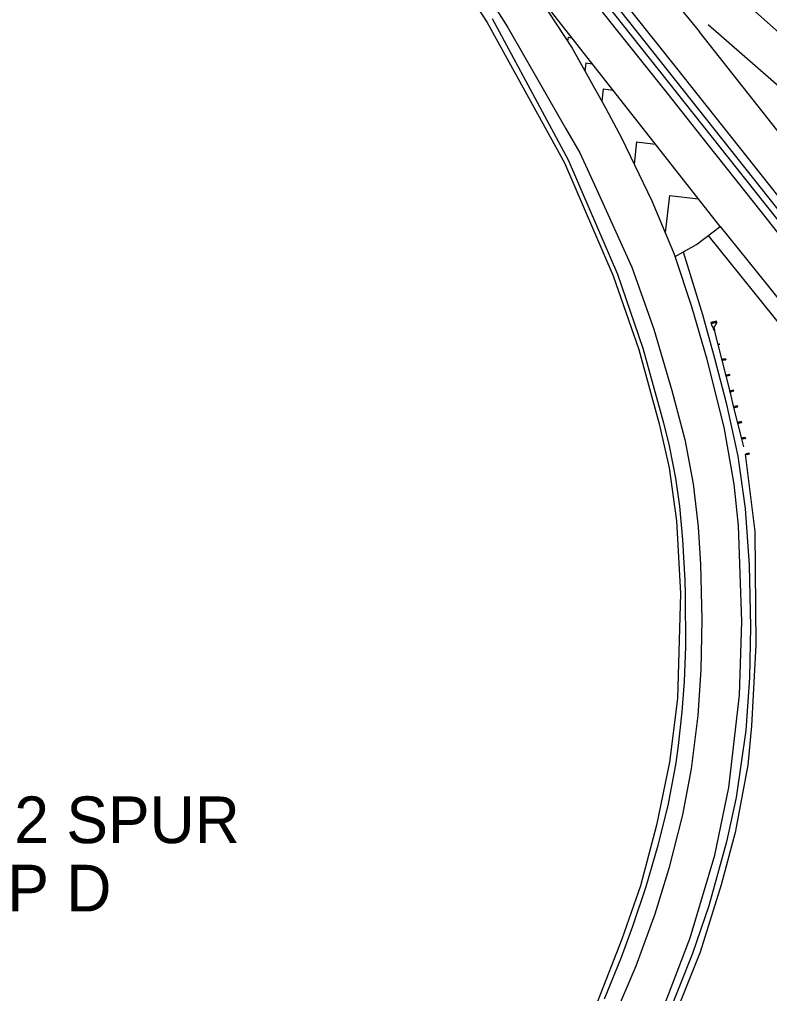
# Model space of a CAD drawing. Extents: x 1855721 to 1876784, y 662259 to 674089.
# Drawn here: x 1856991.1 to 1857280.3, y 672641.1 to 673016.5 of the extents above; entities that cross this region are included whole.
import ezdxf

# ---------------------------------------------------------------- set-up
doc = ezdxf.new("R2010")
doc.units = 0
for name, color, linetype in [('_CIVIL_CONSTRUCTION', 7, 'Continuous'), ('GE_X_Alignment_100_Cardinal_Points', 7, 'Continuous'), ('GE_X_Alignment_100_Curve_Data', 7, 'Continuous'), ('GE_X_Alignment_100_Distances', 7, 'Continuous'), ('GE_X_Alignment_100_Stations', 7, 'Continuous'), ('RD_P_Anchor_Assembly', 7, 'Continuous'), ('RD_P_GR_Lt', 7, 'Continuous'), ('RD_P_GR_Rt', 7, 'Continuous'), ('SC_Scratch1', 7, 'Continuous')]:
    doc.layers.add(name, color=color, linetype=linetype)

msp = doc.modelspace()

# ---------------------------------------------------------------- linework, layer by layer
at = {"layer": '_CIVIL_CONSTRUCTION'}
for points in [[(1857095.78, 673228.1), (1857114.49, 673202.22), (1857151.09, 673154.99), (1857188.96, 673108.49), (1857213.25, 673080.94), (1857233.21, 673059.79), (1857266.95, 673026.66), (1857297.61, 672999.22), (1857331.92, 672970.01), (1857354.64, 672952.14), (1857378.96, 672934.19), (1857405.47, 672915.96), (1857444.17, 672891.21), (1857478.21, 672872.92), (1857508.9, 672856.52), (1857540.29, 672842.86)], [(1857171.86, 673025.53), (1857179.34, 673013.47), (1857191.48, 672992.33), (1857201.68, 672974.59), (1857207.13, 672965.11), (1857213.52, 672951.13), (1857227.26, 672921.04), (1857235.73, 672897.13), (1857242.6, 672873.46), (1857247.6, 672854.66), (1857250.84, 672837.54), (1857252.79, 672820.89), (1857253.73, 672806.43), (1857254.19, 672785.23), (1857253.79, 672765.79), (1857252.61, 672748.23), (1857250.04, 672727.65), (1857246.7, 672709.94), (1857241.52, 672689.28), (1857236.06, 672671.63), (1857228.77, 672651.61), (1857220.56, 672632.38)], [(1857243.92, 672925.11), (1857252.08, 672929.78), (1857261.29, 672936.7)], [(1857261.29, 672936.7), (1857279.32, 672914.23), (1857304.19, 672883.15), (1857336.23, 672842.95), (1857372.14, 672797.66), (1857396.11, 672767.44), (1857422.69, 672733.98), (1857450.63, 672698.81), (1857476.52, 672666.19), (1857485.3, 672655.13)]]:
    msp.add_lwpolyline(points, dxfattribs=at)
at = {"layer": 'GE_X_Alignment_100_Cardinal_Points'}
for p, q in [((1857314.11, 672964.34), (1857256.6, 673014.38)), ((1857300.27, 672952.18), (1857253.23, 673011.76))]:
    msp.add_line(p, q, dxfattribs=at)
msp.add_lwpolyline([(1857261.29, 672936.7), (1857188.59, 673029.16), (1857204.15, 673005.49), (1857217.07, 672982.41), (1857223.18, 672970.87), (1857234.86, 672946.59), (1857243.92, 672925.11)], dxfattribs=at)
at = {"layer": 'GE_X_Alignment_100_Curve_Data'}
for points in [[(1857509.2, 672663.72), (1857480.95, 672699.51), (1857449.94, 672738.8), (1857424.19, 672771.33), (1857385.55, 672820.03), (1857367.65, 672842.6), (1857324.08, 672897.51), (1857304.91, 672921.66), (1857283.48, 672948.66), (1857244.56, 672997.72), (1857227.86, 673018.64), (1857203.78, 673048.81), (1857185.85, 673071.47), (1857128.32, 673144.31), (1857108.27, 673169.55), (1857084.52, 673199.44), (1857058.84, 673231.89)], [(1857501.24, 672660.32), (1857469.78, 672699.79), (1857426.19, 672754.46), (1857391.7, 672797.83), (1857362.81, 672834.28), (1857343.14, 672859.04), (1857322.77, 672884.63), (1857297.43, 672916.66), (1857274.68, 672945.61), (1857256.27, 672968.76), (1857240.79, 672988.24), (1857227.01, 673005.61), (1857212.23, 673024.24), (1857195.7, 673045.09), (1857181.09, 673063.54), (1857168.6, 673079.32), (1857156.34, 673094.81), (1857141.98, 673112.95), (1857127.65, 673131.05), (1857110.44, 673152.8), (1857097.62, 673169.01), (1857085.15, 673184.77), (1857069.24, 673204.89), (1857053.62, 673224.64)], [(1856995.67, 672399.27), (1857022.49, 672417.27), (1857072.19, 672450.65), (1857096.64, 672467.55), (1857127.39, 672490.89), (1857153.4, 672513.58), (1857176.68, 672537.32), (1857196.32, 672561.17), (1857214.39, 672587.65), (1857226.83, 672609.47), (1857240.75, 672639.06), (1857249.68, 672662.48), (1857259.18, 672694.4), (1857264.64, 672720.46), (1857268.75, 672756.02), (1857269.66, 672784.43), (1857268.35, 672821.5), (1857266.68, 672837.43), (1857262.78, 672859.39), (1857256.19, 672885.4), (1857250.31, 672905.75), (1857243.92, 672925.11)]]:
    msp.add_lwpolyline(points, dxfattribs=at)
at = {"layer": 'GE_X_Alignment_100_Distances'}
msp.add_lwpolyline([(1857050.52, 673266.41), (1857141.34, 673148.16), (1857253.23, 673011.76)], dxfattribs=at)
at = {"layer": 'GE_X_Alignment_100_Stations'}
for p, q in [((1857202.63, 673009.65), (1857202.45, 673008.08)), ((1857202.63, 673009.65), (1857204.06, 673009.48)), ((1857209.46, 672999.75), (1857209.1, 672996.64)), ((1857209.46, 672999.75), (1857211.94, 672999.46)), ((1857216.13, 672989.71), (1857215.59, 672985.05)), ((1857216.13, 672989.71), (1857219.96, 672989.26)), ((1857229.06, 672969.31), (1857228.07, 672960.71)), ((1857229.06, 672969.31), (1857236.31, 672968.48)), ((1857241.68, 672948.66), (1857240.04, 672934.38)), ((1857241.68, 672948.66), (1857252.91, 672947.37))]:
    msp.add_line(p, q, dxfattribs=at)
at = {"layer": 'RD_P_Anchor_Assembly'}
for p, q in [((1857258.85, 672897.31), (1857260.37, 672891.24)), ((1857260.35, 672891.31), (1857260.43, 672890.99)), ((1857260.37, 672891.31), (1857260.35, 672891.31)), ((1857260.36, 672891.27), (1857260.82, 672891.39)), ((1857260.37, 672891.31), (1857260.41, 672891.16)), ((1857260.37, 672891.24), (1857261.89, 672885.18)), ((1857260.38, 672891.21), (1857260.84, 672891.33)), ((1857260.85, 672891.27), (1857260.41, 672891.16)), ((1857260.86, 672891.26), (1857260.41, 672891.15)), ((1857260.41, 672891.15), (1857260.45, 672890.99)), ((1857260.45, 672890.99), (1857260.43, 672890.99)), ((1857260.83, 672891.43), (1857260.81, 672891.42)), ((1857260.81, 672891.42), (1857260.85, 672891.27)), ((1857260.94, 672891.42), (1857260.82, 672891.39)), ((1857260.83, 672891.44), (1857260.84, 672891.45)), ((1857260.83, 672891.43), (1857260.91, 672891.11)), ((1857260.84, 672891.44), (1857260.88, 672891.29)), ((1857260.96, 672891.36), (1857260.84, 672891.33)), ((1857260.85, 672891.42), (1857260.9, 672891.43)), ((1857260.86, 672891.26), (1857260.89, 672891.11)), ((1857260.87, 672891.32), (1857260.92, 672891.33)), ((1857260.87, 672891.29), (1857260.88, 672891.29)), ((1857260.91, 672891.11), (1857260.89, 672891.11)), ((1857260.91, 672891.42), (1857260.93, 672891.35)), ((1857260.94, 672891.42), (1857260.96, 672891.36)), ((1857261.85, 672885.34), (1857261.86, 672885.35)), ((1857261.85, 672885.34), (1857261.93, 672885.02)), ((1857261.86, 672885.35), (1857261.9, 672885.19)), ((1857261.89, 672885.18), (1857263.4, 672879.12)), ((1857261.9, 672885.19), (1857262.34, 672885.3)), ((1857261.9, 672885.18), (1857262.35, 672885.29)), ((1857261.9, 672885.18), (1857261.94, 672885.03)), ((1857261.93, 672885.02), (1857261.94, 672885.03)), ((1857262.21, 672885.4), (1857262.33, 672885.43)), ((1857262.21, 672885.4), (1857262.22, 672885.34)), ((1857262.22, 672885.34), (1857262.35, 672885.37)), ((1857262.24, 672885.41), (1857262.26, 672885.34)), ((1857262.29, 672885.44), (1857262.25, 672885.43)), ((1857262.32, 672885.34), (1857262.27, 672885.33)), ((1857263.26, 672885.76), (1857262.29, 672885.52)), ((1857262.29, 672885.51), (1857262.3, 672885.47)), ((1857262.29, 672885.47), (1857262.33, 672885.31)), ((1857262.3, 672885.47), (1857262.29, 672885.47)), ((1857262.32, 672885.48), (1857262.3, 672885.47)), ((1857262.31, 672885.46), (1857262.34, 672885.3)), ((1857262.31, 672885.46), (1857262.32, 672885.46)), ((1857262.32, 672885.48), (1857262.41, 672885.13)), ((1857262.32, 672885.46), (1857262.4, 672885.14)), ((1857263.29, 672885.67), (1857262.33, 672885.43)), ((1857262.34, 672885.32), (1857262.33, 672885.31)), ((1857263.31, 672885.61), (1857262.35, 672885.37)), ((1857262.35, 672885.29), (1857262.39, 672885.14)), ((1857262.41, 672885.13), (1857262.38, 672885.12)), ((1857262.38, 672885.12), (1857262.39, 672885.08)), ((1857262.39, 672885.14), (1857262.4, 672885.14)), ((1857263.37, 672885.32), (1857262.41, 672885.07)), ((1857263.27, 672885.75), (1857263.38, 672885.33)), ((1857263.36, 672879.28), (1857263.44, 672878.96)), ((1857263.36, 672879.28), (1857263.38, 672879.28)), ((1857263.38, 672879.28), (1857263.42, 672879.13)), ((1857263.4, 672879.12), (1857264.92, 672873.05)), ((1857263.42, 672879.13), (1857263.86, 672879.24)), ((1857263.42, 672879.12), (1857263.86, 672879.23)), ((1857263.42, 672879.12), (1857263.46, 672878.96)), ((1857263.44, 672878.96), (1857263.46, 672878.96)), ((1857263.73, 672879.33), (1857263.85, 672879.36)), ((1857263.73, 672879.33), (1857263.74, 672879.27)), ((1857263.74, 672879.27), (1857263.86, 672879.3)), ((1857263.75, 672879.35), (1857263.77, 672879.27)), ((1857263.81, 672879.38), (1857263.76, 672879.36)), ((1857263.83, 672879.28), (1857263.79, 672879.27)), ((1857263.8, 672879.44), (1857263.81, 672879.41)), ((1857263.82, 672879.41), (1857263.8, 672879.4)), ((1857263.8, 672879.4), (1857263.84, 672879.25)), ((1857264.78, 672879.7), (1857263.81, 672879.46)), ((1857263.84, 672879.41), (1857263.81, 672879.41)), ((1857263.82, 672879.39), (1857263.84, 672879.4)), ((1857263.82, 672879.39), (1857263.86, 672879.24)), ((1857263.84, 672879.41), (1857263.92, 672879.06)), ((1857263.84, 672879.4), (1857263.92, 672879.08)), ((1857263.86, 672879.25), (1857263.84, 672879.25)), ((1857264.81, 672879.6), (1857263.85, 672879.36)), ((1857264.82, 672879.54), (1857263.86, 672879.3)), ((1857263.86, 672879.23), (1857263.9, 672879.07)), ((1857263.9, 672879.07), (1857263.92, 672879.08)), ((1857263.92, 672879.06), (1857263.9, 672879.06)), ((1857263.9, 672879.06), (1857263.91, 672879.02)), ((1857264.89, 672879.25), (1857263.92, 672879.01)), ((1857264.79, 672879.69), (1857264.89, 672879.26)), ((1857264.88, 672873.21), (1857264.89, 672873.22)), ((1857264.88, 672873.21), (1857264.96, 672872.89)), ((1857264.89, 672873.22), (1857264.93, 672873.07)), ((1857264.92, 672873.05), (1857266.43, 672866.99)), ((1857264.93, 672873.07), (1857265.38, 672873.18)), ((1857264.94, 672873.05), (1857265.38, 672873.16)), ((1857264.94, 672873.05), (1857264.97, 672872.9)), ((1857264.96, 672872.89), (1857264.97, 672872.9)), ((1857265.24, 672873.27), (1857265.36, 672873.3)), ((1857265.24, 672873.27), (1857265.26, 672873.21)), ((1857265.26, 672873.21), (1857265.38, 672873.24)), ((1857265.27, 672873.29), (1857265.29, 672873.21)), ((1857265.33, 672873.31), (1857265.28, 672873.3)), ((1857265.35, 672873.22), (1857265.3, 672873.2)), ((1857265.32, 672873.38), (1857265.33, 672873.34)), ((1857265.32, 672873.34), (1857265.36, 672873.19)), ((1857265.33, 672873.34), (1857265.32, 672873.34)), ((1857266.29, 672873.63), (1857265.33, 672873.39)), ((1857265.35, 672873.35), (1857265.33, 672873.34)), ((1857265.34, 672873.33), (1857265.38, 672873.18)), ((1857265.34, 672873.33), (1857265.35, 672873.33)), ((1857265.35, 672873.35), (1857265.44, 672873)), ((1857265.35, 672873.33), (1857265.43, 672873.01)), ((1857266.32, 672873.54), (1857265.36, 672873.3)), ((1857265.37, 672873.19), (1857265.36, 672873.19)), ((1857266.34, 672873.48), (1857265.38, 672873.24)), ((1857265.38, 672873.16), (1857265.42, 672873.01)), ((1857265.42, 672873.01), (1857265.43, 672873.01)), ((1857265.44, 672873), (1857265.42, 672872.99)), ((1857265.42, 672872.99), (1857265.43, 672872.96)), ((1857266.4, 672873.19), (1857265.44, 672872.95)), ((1857266.3, 672873.63), (1857266.41, 672873.2)), ((1857266.83, 672867.32), (1857266.84, 672867.28)), ((1857267.81, 672867.57), (1857266.84, 672867.33)), ((1857266.87, 672867.29), (1857266.84, 672867.28)), ((1857266.84, 672867.28), (1857266.87, 672867.12)), ((1857266.85, 672867.28), (1857266.84, 672867.28)), ((1857266.85, 672867.27), (1857266.89, 672867.11)), ((1857266.85, 672867.27), (1857266.87, 672867.27)), ((1857266.87, 672867.29), (1857266.95, 672866.94)), ((1857266.87, 672867.27), (1857266.95, 672866.95)), ((1857267.84, 672867.48), (1857266.88, 672867.24)), ((1857267.86, 672867.42), (1857266.89, 672867.18)), ((1857267.82, 672867.56), (1857267.93, 672867.14)), ((1857266.39, 672867.15), (1857266.47, 672866.83)), ((1857266.39, 672867.15), (1857266.41, 672867.15)), ((1857266.41, 672867.15), (1857266.45, 672867)), ((1857266.43, 672866.99), (1857267.95, 672860.93)), ((1857266.45, 672867), (1857266.89, 672867.11)), ((1857266.45, 672866.99), (1857266.89, 672867.1)), ((1857266.45, 672866.99), (1857266.49, 672866.84)), ((1857266.47, 672866.83), (1857266.49, 672866.84)), ((1857266.76, 672867.21), (1857266.88, 672867.24)), ((1857266.76, 672867.21), (1857266.77, 672867.15)), ((1857266.77, 672867.15), (1857266.89, 672867.18)), ((1857266.78, 672867.22), (1857266.8, 672867.15)), ((1857266.84, 672867.25), (1857266.79, 672867.24)), ((1857266.87, 672867.15), (1857266.82, 672867.14)), ((1857266.89, 672867.13), (1857266.87, 672867.12)), ((1857266.89, 672867.1), (1857266.93, 672866.95)), ((1857266.93, 672866.95), (1857266.95, 672866.95)), ((1857266.95, 672866.94), (1857266.93, 672866.93)), ((1857266.93, 672866.93), (1857266.94, 672866.89)), ((1857267.92, 672867.13), (1857266.95, 672866.88)), ((1857267.91, 672861.09), (1857267.99, 672860.77)), ((1857267.91, 672861.09), (1857267.93, 672861.09)), ((1857267.93, 672861.09), (1857267.96, 672860.94)), ((1857267.95, 672860.93), (1857269.46, 672854.86)), ((1857267.96, 672860.94), (1857268.41, 672861.05)), ((1857267.97, 672860.93), (1857268.41, 672861.04)), ((1857267.97, 672860.93), (1857268.01, 672860.77)), ((1857267.99, 672860.77), (1857268.01, 672860.77)), ((1857268.27, 672861.14), (1857268.39, 672861.17)), ((1857268.27, 672861.14), (1857268.29, 672861.08)), ((1857268.29, 672861.08), (1857268.41, 672861.11)), ((1857268.3, 672861.16), (1857268.32, 672861.08)), ((1857268.36, 672861.18), (1857268.31, 672861.17)), ((1857268.38, 672861.09), (1857268.33, 672861.08)), ((1857268.35, 672861.25), (1857268.36, 672861.22)), ((1857268.37, 672861.22), (1857268.35, 672861.21)), ((1857268.35, 672861.21), (1857268.39, 672861.06)), ((1857269.32, 672861.51), (1857268.36, 672861.27)), ((1857268.38, 672861.22), (1857268.36, 672861.22)), ((1857268.37, 672861.2), (1857268.39, 672861.21)), ((1857268.37, 672861.2), (1857268.41, 672861.05)), ((1857268.38, 672861.22), (1857268.47, 672860.87)), ((1857269.36, 672861.41), (1857268.39, 672861.17)), ((1857268.39, 672861.21), (1857268.47, 672860.89)), ((1857268.4, 672861.06), (1857268.39, 672861.06)), ((1857269.37, 672861.35), (1857268.41, 672861.11)), ((1857268.41, 672861.04), (1857268.45, 672860.88)), ((1857268.45, 672860.88), (1857268.47, 672860.89)), ((1857268.47, 672860.87), (1857268.45, 672860.87)), ((1857268.45, 672860.87), (1857268.46, 672860.83)), ((1857269.43, 672861.06), (1857268.47, 672860.82)), ((1857269.33, 672861.5), (1857269.44, 672861.07)), ((1857269.42, 672855.02), (1857269.44, 672855.03)), ((1857269.42, 672855.02), (1857269.5, 672854.7)), ((1857269.44, 672855.03), (1857269.48, 672854.88)), ((1857269.46, 672854.86), (1857270.22, 672851.83)), ((1857269.48, 672854.88), (1857269.92, 672854.99)), ((1857269.48, 672854.86), (1857269.93, 672854.97)), ((1857269.48, 672854.86), (1857269.52, 672854.71)), ((1857269.5, 672854.7), (1857269.52, 672854.71)), ((1857269.79, 672855.08), (1857269.91, 672855.11)), ((1857269.79, 672855.08), (1857269.8, 672855.02)), ((1857269.8, 672855.02), (1857269.93, 672855.05)), ((1857269.82, 672855.1), (1857269.83, 672855.02)), ((1857269.87, 672855.12), (1857269.83, 672855.11)), ((1857269.9, 672855.03), (1857269.85, 672855.01)), ((1857270.84, 672855.44), (1857269.87, 672855.2)), ((1857269.87, 672855.19), (1857269.88, 672855.15)), ((1857269.87, 672855.15), (1857269.9, 672855)), ((1857269.88, 672855.15), (1857269.87, 672855.15)), ((1857269.9, 672855.16), (1857269.88, 672855.15)), ((1857269.88, 672855.14), (1857269.92, 672854.99)), ((1857269.88, 672855.14), (1857269.9, 672855.14)), ((1857269.9, 672855.16), (1857269.99, 672854.81)), ((1857269.9, 672855.14), (1857269.98, 672854.82)), ((1857270.87, 672855.35), (1857269.91, 672855.11)), ((1857269.92, 672855), (1857269.91, 672855)), ((1857270.89, 672855.29), (1857269.93, 672855.05)), ((1857269.93, 672854.97), (1857269.96, 672854.82)), ((1857269.96, 672854.82), (1857269.98, 672854.82)), ((1857269.99, 672854.81), (1857269.96, 672854.8)), ((1857269.96, 672854.8), (1857269.97, 672854.76)), ((1857270.95, 672855), (1857269.98, 672854.76)), ((1857270.85, 672855.44), (1857270.96, 672855.01)), ((1857270.94, 672848.96), (1857271.02, 672848.64)), ((1857270.94, 672848.96), (1857270.96, 672848.96)), ((1857270.96, 672848.96), (1857271, 672848.81)), ((1857271, 672848.81), (1857271.44, 672848.92)), ((1857271, 672848.8), (1857271.44, 672848.91)), ((1857271, 672848.8), (1857271.04, 672848.65)), ((1857271.02, 672848.64), (1857271.04, 672848.65)), ((1857271.3, 672849.02), (1857271.43, 672849.05)), ((1857271.3, 672849.02), (1857271.32, 672848.96)), ((1857271.32, 672848.96), (1857271.44, 672848.99)), ((1857271.33, 672849.03), (1857271.35, 672848.96)), ((1857271.39, 672849.06), (1857271.34, 672849.05)), ((1857271.41, 672848.96), (1857271.36, 672848.95)), ((1857271.38, 672849.13), (1857271.39, 672849.09)), ((1857271.38, 672849.09), (1857271.42, 672848.93)), ((1857271.4, 672849.09), (1857271.38, 672849.09)), ((1857272.35, 672849.38), (1857271.39, 672849.14)), ((1857271.41, 672849.1), (1857271.39, 672849.09)), ((1857271.4, 672849.08), (1857271.44, 672848.92)), ((1857271.4, 672849.08), (1857271.42, 672849.08)), ((1857271.41, 672849.1), (1857271.5, 672848.74)), ((1857271.42, 672849.08), (1857271.5, 672848.76)), ((1857271.43, 672848.94), (1857271.42, 672848.93)), ((1857272.39, 672849.29), (1857271.43, 672849.05)), ((1857272.4, 672849.23), (1857271.44, 672848.99)), ((1857271.44, 672848.91), (1857271.48, 672848.76)), ((1857271.48, 672848.76), (1857271.5, 672848.76)), ((1857271.5, 672848.74), (1857271.48, 672848.74)), ((1857271.48, 672848.74), (1857271.49, 672848.7)), ((1857272.47, 672848.94), (1857271.5, 672848.69)), ((1857272.37, 672849.37), (1857272.47, 672848.95))]:
    msp.add_line(p, q, dxfattribs=at)
for centre, start, end in [((1857262.3, 672885.51), 104.0355, 194.0355), ((1857262.4, 672885.08), 194.0355, 284.0355), ((1857263.26, 672885.75), 14.0355, 104.0355), ((1857263.37, 672885.33), 284.0355, 14.0355), ((1857263.81, 672879.45), 104.0355, 194.0355), ((1857263.92, 672879.02), 194.0355, 284.0355), ((1857264.78, 672879.69), 14.0355, 104.0355), ((1857264.88, 672879.26), 284.0355, 14.0355), ((1857265.33, 672873.38), 104.0355, 194.0355), ((1857265.43, 672872.96), 194.0355, 284.0355), ((1857266.29, 672873.62), 14.0355, 104.0355), ((1857266.4, 672873.2), 284.0355, 14.0355), ((1857266.84, 672867.32), 104.0355, 194.0355), ((1857267.81, 672867.56), 14.0355, 104.0355), ((1857266.95, 672866.89), 194.0355, 284.0355), ((1857267.92, 672867.14), 284.0355, 14.0355), ((1857268.36, 672861.26), 104.0355, 194.0355), ((1857268.47, 672860.83), 194.0355, 284.0355), ((1857269.32, 672861.5), 14.0355, 104.0355), ((1857269.43, 672861.07), 284.0355, 14.0355), ((1857269.88, 672855.19), 104.0355, 194.0355), ((1857269.98, 672854.77), 194.0355, 284.0355), ((1857270.84, 672855.43), 14.0355, 104.0355), ((1857270.95, 672855.01), 284.0355, 14.0355), ((1857271.39, 672849.13), 104.0355, 194.0355), ((1857271.5, 672848.7), 194.0355, 284.0355), ((1857272.36, 672849.37), 14.0355, 104.0355), ((1857272.46, 672848.95), 284.0355, 14.0355)]:
    msp.add_arc(centre, 0.01, start, end, dxfattribs=at)
for centre, major_axis, ratio, start_param, end_param in [((1857260.36, 672891.24), (0.025, -0.101), 0.312583, 3.061844, 6.362934), ((1857260.9, 672891.42), (-0.0135, -0.0034), 0.929688, 3.345604, 4.722982), ((1857260.92, 672891.35), (-0.0136, -0.0034), 0.929688, 1.586202, 2.897406), ((1857262.25, 672885.41), (0.0135, 0.0034), 0.929688, 1.560203, 2.937581), ((1857262.27, 672885.34), (0.0136, 0.0034), 0.929688, 3.385779, 4.696983), ((1857263.3, 672885.64), (0.025, -0.101), 0.312583, 6.203436, 9.504527), ((1857263.77, 672879.35), (0.0135, 0.0034), 0.929688, 1.560203, 2.937581), ((1857263.78, 672879.28), (0.0136, 0.0034), 0.929688, 3.385779, 4.696983), ((1857264.82, 672879.57), (0.025, -0.101), 0.312583, 6.203436, 9.504527), ((1857265.28, 672873.29), (0.0135, 0.0034), 0.929688, 1.560203, 2.937581), ((1857265.3, 672873.22), (0.0136, 0.0034), 0.929688, 3.385779, 4.696983), ((1857266.33, 672873.51), (0.025, -0.101), 0.312583, 6.203436, 9.504527), ((1857267.85, 672867.45), (0.025, -0.101), 0.312583, 6.203436, 9.504527), ((1857266.8, 672867.22), (0.0135, 0.0034), 0.929688, 1.560203, 2.937581), ((1857266.82, 672867.15), (0.0136, 0.0034), 0.929688, 3.385779, 4.696983), ((1857268.31, 672861.16), (0.0135, 0.0034), 0.929688, 1.560203, 2.937581), ((1857268.33, 672861.09), (0.0136, 0.0034), 0.929688, 3.385779, 4.696983), ((1857269.37, 672861.38), (0.025, -0.101), 0.312583, 6.203436, 9.504527), ((1857269.83, 672855.1), (0.0135, 0.0034), 0.929688, 1.560203, 2.937581), ((1857269.85, 672855.03), (0.0136, 0.0034), 0.929688, 3.385779, 4.696983), ((1857270.88, 672855.32), (0.025, -0.101), 0.312583, 6.203436, 9.504527), ((1857271.34, 672849.03), (0.0135, 0.0034), 0.929688, 1.560203, 2.937581), ((1857271.36, 672848.96), (0.0136, 0.0034), 0.929688, 3.385779, 4.696983), ((1857272.4, 672849.26), (0.025, -0.101), 0.312583, 6.203436, 9.504527)]:
    msp.add_ellipse(centre, major_axis=major_axis, ratio=ratio, start_param=start_param, end_param=end_param, dxfattribs=at)
at = {"layer": 'RD_P_GR_Lt'}
msp.add_lwpolyline([(1857270.94, 672848.96), (1857274.63, 672819.15), (1857275.06, 672775.39), (1857273.35, 672744.2), (1857271.97, 672729.14), (1857266.99, 672703.12), (1857261.58, 672682.93), (1857253.6, 672657.05), (1857244.56, 672634.53), (1857230.64, 672605.17), (1857218.38, 672583.06), (1857205.98, 672565.16), (1857189.18, 672543.48)], dxfattribs=at)
at = {"layer": 'RD_P_GR_Rt'}
for p, q in [((1857259.87, 672900.22), (1857257.68, 672899.69)), ((1857259.95, 672899.88), (1857257.76, 672899.35)), ((1857260, 672899.68), (1857257.82, 672899.15)), ((1857258.77, 672896.81), (1857258.53, 672897.81)), ((1857260, 672899.68), (1857258.92, 672897.9)), ((1857259.16, 672896.91), (1857258.92, 672897.9)), ((1857260, 672899.68), (1857259.87, 672900.22)), ((1857259.16, 672896.91), (1857258.77, 672896.81))]:
    msp.add_line(p, q, dxfattribs=at)
for points in [[(1857024.47, 673211.43), (1857061.26, 673166.23), (1857093.28, 673126.47), (1857127.57, 673081.64), (1857150.32, 673047.87), (1857171.46, 673015.38), (1857201.22, 672961.26), (1857220.02, 672917.75), (1857229.93, 672889.26), (1857237.71, 672860.66), (1857241.62, 672843.68), (1857244.44, 672823.32), (1857245.99, 672795.25), (1857244.81, 672754.8), (1857241.66, 672730.29), (1857236.72, 672706), (1857230.57, 672682.56), (1857223.35, 672662.08), (1857214.27, 672638.69), (1857203.64, 672617.5), (1857187.67, 672591.8), (1857169.22, 672567.8)], [(1857257.68, 672899.69), (1857258.02, 672898.38), (1857258.53, 672897.81)]]:
    msp.add_lwpolyline(points, dxfattribs=at)
at = {"layer": 'SC_Scratch1'}
for points in [[(1857506.27, 672661.92), (1857419.93, 672771.16), (1857315.59, 672902.87), (1857226.39, 673015.29), (1857156.27, 673103.7), (1857102.52, 673171.6), (1857037.75, 673253.29), (1856965.28, 673344.85), (1856882.51, 673448.91), (1856802.82, 673549.45), (1856753.58, 673611.84), (1856715.89, 673659.59)], [(1856712.69, 673658.93), (1856740.72, 673623.65), (1856759.09, 673600.43), (1856797.94, 673551.31), (1856903.56, 673418.23), (1856938.71, 673373.91), (1856970.61, 673333.81), (1857008.56, 673285.85), (1857035.35, 673252.02), (1857055.95, 673226.05), (1857079.8, 673196), (1857110.23, 673157.64), (1857164.72, 673088.94), (1857203.73, 673039.74), (1857244.27, 672988.5), (1857277.96, 672946.15), (1857290.57, 672930.23), (1857322.95, 672889.42), (1857361.11, 672841.48), (1857423.44, 672762.67), (1857504.02, 672661.22)], [(1857173.38, 673016.93), (1857202.72, 672962.36), (1857221.73, 672918.37), (1857231.43, 672889.84), (1857239.36, 672861.1), (1857241.58, 672852.23), (1857244.01, 672839.69), (1857245.52, 672828.93), (1857246.76, 672815.94), (1857247.59, 672800.4), (1857247.76, 672794.66), (1857247.83, 672774.8), (1857247.36, 672761.33), (1857246.54, 672749.63), (1857245.1, 672736.63), (1857244.14, 672730.02), (1857241.18, 672714.21), (1857237.28, 672698.16), (1857232.61, 672682.21), (1857227.49, 672666.93), (1857223.08, 672654.99), (1857216.49, 672638.96)], [(1857256.46, 672933.36), (1857281.9, 672901.72), (1857304.56, 672873.5), (1857332.58, 672838.46), (1857359.52, 672804.43), (1857384.51, 672772.92), (1857408.61, 672742.96), (1857428.61, 672718.7), (1857451.33, 672691.81), (1857465.39, 672674.93), (1857472.63, 672666.01), (1857472.41, 672665.79), (1857481.82, 672654)], [(1857247.04, 672926.89), (1857254.48, 672902.82), (1857259.13, 672885.93), (1857263.55, 672868.8), (1857268.11, 672848.25), (1857270.87, 672828.08), (1857272.43, 672806.17), (1857272.95, 672782.44), (1857272.55, 672762.94), (1857271.09, 672742.44), (1857267.4, 672716.66), (1857263.73, 672699.58), (1857256.86, 672674.93), (1857250.6, 672656.47), (1857240.62, 672631.38)]]:
    msp.add_lwpolyline(points, dxfattribs=at)

# ---------------------------------------------------------------- texts
for s, p in [('OTT-2 SPUR', (1856932.99, 672699.03)), ('RAMP D', (1856932.99, 672672.7))]:
    msp.add_text(s, height=18, dxfattribs=at).set_placement(p)

doc.saveas('drawing.dxf')
